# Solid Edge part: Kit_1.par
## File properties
Sűrűség: 0,000 kg/m^3
Pontosság: 0,990
Author: bmolnar
Last saved by: bmolnar
Revision: 79
Username: bmolnar
Dokumentum tartalom típus: 0
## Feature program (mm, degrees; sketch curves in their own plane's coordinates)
base feature "unnamed BaseFeature 1"
sketch for "unnamed Cutout 1" plane through (-0.0012, 0, 85.35) normal (0, 0, -1) x-axis (-1, 0, 0)
  circle centre (-0.0012, 0) radius 8
extrude "unnamed Cutout 1" cut through along -normal
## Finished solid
Body 1: solid body, 42 faces, 59 edges, 25 vertices, 1 internal void.
  Faces by surface: cylinder 15, cone 13, plane 11, torus 3
  Edges by curve: circle 45, line 14
Bounding box of the edges (mm; curved faces can reach further): 68.000 x 67.800 x 14.650, from (-34, -32.35, 85.35) to (34, 35.45, 100).
Cylindrical faces by radius (mm): R1.5 x2, R3 x4, R8 x1, R8.27 x1, R8.85 x1, R9 x1, R10.25 x1, R19.25 x1, R29.65 x1, R32.35 x1, R34 x1
Conical faces (half-angle, radius in mm at the cone's reference point): 7 deg R9.5925 x1, 14 deg R8.135 x1, 14 deg R8.4811 x1, 17 deg R8.135 x1, 23 deg R8.829 x1, 42.5 deg R8.1233 x1, 45 deg R9.1 x2, 45 deg R18.75 x1, 84 deg R76.3675 x2, 85 deg R9.9463 x1, 87 deg R8.1765 x1
Toroidal faces (ring radius, tube radius in mm): R8.8057 r0.2025 x1, R9.2522 r0.2925 x1, R20.05 r0.8 x1
Planar faces by outward normal: +z 7, -z 2, oblique 2
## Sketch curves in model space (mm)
circle centre (0, 0, 85.35) radius 8
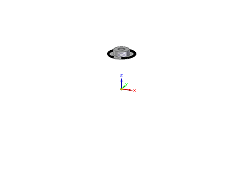
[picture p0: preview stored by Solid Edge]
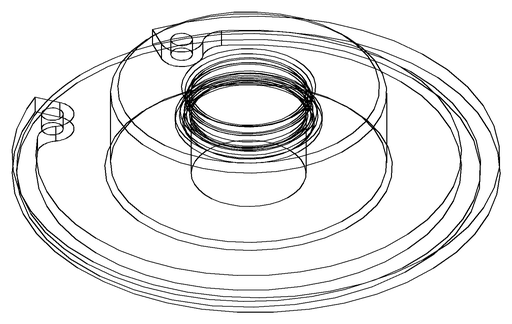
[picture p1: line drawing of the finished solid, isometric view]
